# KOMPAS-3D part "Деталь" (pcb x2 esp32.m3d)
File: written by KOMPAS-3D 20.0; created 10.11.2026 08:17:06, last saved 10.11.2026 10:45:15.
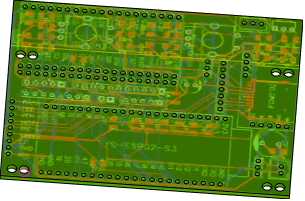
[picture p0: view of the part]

Document properties: Полное имя файла: D:\RicWork\Project-EPS32\box_compas\esp32\pcb x2 esp32.m3d

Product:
- Part/product: Деталь
    Масса: 0.0653727

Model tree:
1. Эскиз:1
2. Элемент выдавливания:1
     Расстояние 1 = 1.5
3. Эскиз:2  (with: Элемент выдавливания:1)
4. Элемент выдавливания:2
     Расстояние 2 = 1.5
5. Массив по сетке:1  (with: Элемент выдавливания:2, Эскиз:2, Элемент выдавливания:1)  (4 pattern instances)
     Шаг 1 = 75.9; Угол раствора = 90; Шаг 2 = 44.2
6. Эскиз:3  (with: Элемент выдавливания:1)
7. Эскиз:4  (with: Элемент выдавливания:1, Элемент выдавливания:2)
8. Элемент выдавливания:3
     Расстояние 2 = 1.5
9. Массив по сетке:2  (with: Элемент выдавливания:3, Эскиз:4)  (9 pattern instances)
     Шаг 1 = 10; Угол раствора = -90; Шаг 2 = 2.54
10. Эскиз:5  (with: Элемент выдавливания:1, Элемент выдавливания:2, Элемент выдавливания:3)
11. Элемент выдавливания:5
     Расстояние 2 = 1.5
12. Массив по сетке:3  (with: Элемент выдавливания:5, Эскиз:3)  (4 pattern instances)
     Шаг 1 = 76.08; Угол раствора = -90; Шаг 2 = 44.2
13. Эскиз:6  (with: Элемент выдавливания:1)
14. Эскиз:7  (with: Элемент выдавливания:1)
15. Элемент выдавливания:6
     Расстояние 2 = 1.5
16. Массив по сетке:4  (with: Элемент выдавливания:6, Эскиз:7)  (44 pattern instances)
     Шаг 1 = 2.54; Угол раствора = -90; Шаг 2 = 25.4
17. Эскиз:8  (with: Элемент выдавливания:1)
18. Элемент выдавливания:7
     Расстояние 2 = 1.5
19. Массив по сетке:5  (with: Элемент выдавливания:7, Эскиз:8)  (38 pattern instances)
     Шаг 1 = 2.54; Угол раствора = 90; Шаг 2 = 25.4
20. Эскиз:9  (with: Элемент выдавливания:1)
21. Элемент выдавливания:8
     Расстояние 2 = 1.5
22. Массив по сетке:6  (with: Элемент выдавливания:8, Эскиз:9)  (2 pattern instances)
     Шаг 1 = 10; Угол раствора = -90; Шаг 2 = 2.54
23. Эскиз:10  (with: Элемент выдавливания:1)
24. Элемент выдавливания:9
     Расстояние 2 = 1.5
25. Массив по сетке:7  (with: Элемент выдавливания:9, Эскиз:10)  (3 pattern instances)
     Шаг 1 = 10; Угол раствора = -90; Шаг 2 = 2.54
26. Эскиз:11  (with: Элемент выдавливания:1)
27. Элемент выдавливания:10
     Расстояние 2 = 1.5
28. Массив по сетке:8  (with: Элемент выдавливания:10, Эскиз:11)  (3 pattern instances)
     Шаг 1 = 2.54; Угол раствора = 90
29. Эскиз:12  (with: Элемент выдавливания:1)
30. Элемент выдавливания:11
     Расстояние 2 = 1.5
31. Массив по сетке:9  (with: Элемент выдавливания:11, Эскиз:12)  (5 pattern instances)
     Шаг 1 = 2.54; Угол раствора = 90
32. Эскиз:13  (with: Элемент выдавливания:1, Элемент выдавливания:7)
33. Элемент выдавливания:12
     Расстояние 2 = 1.5
34. Массив по сетке:10  (with: Элемент выдавливания:12, Эскиз:13)  (19 pattern instances)
     Шаг 1 = 2.54; Угол раствора = 90
35. Эскиз:14  (with: Элемент выдавливания:1)
36. Элемент выдавливания:13
     Расстояние 2 = 1.5
37. Массив по сетке:11  (with: Элемент выдавливания:13, Эскиз:14)  (8 pattern instances)
     Шаг 1 = 10; Угол раствора = -90; Шаг 2 = 2.54
38. Эскиз:15  (with: Элемент выдавливания:1)
39. Элемент выдавливания:14
     Расстояние 2 = 1.5
40. Массив по сетке:12  (with: Элемент выдавливания:14, Эскиз:15)  (3 pattern instances)
     Шаг 1 = 10; Угол раствора = -90; Шаг 2 = 2.54
41. Эскиз:16  (with: Элемент выдавливания:1)
42. Элемент выдавливания:15
     Расстояние 2 = 1.5
43. Массив по сетке:13  (with: Элемент выдавливания:15, Эскиз:16)  (4 pattern instances)
     Шаг 1 = 10; Угол раствора = -90; Шаг 2 = 2.54

Referenced files in D:\RicWork\Project-EPS32\box_compas\esp32\: pcb x2 esp32_up.png, pcb x2 esp32.png
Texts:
  pcb x2 esp32_up.png
  pcb x2 esp32.png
